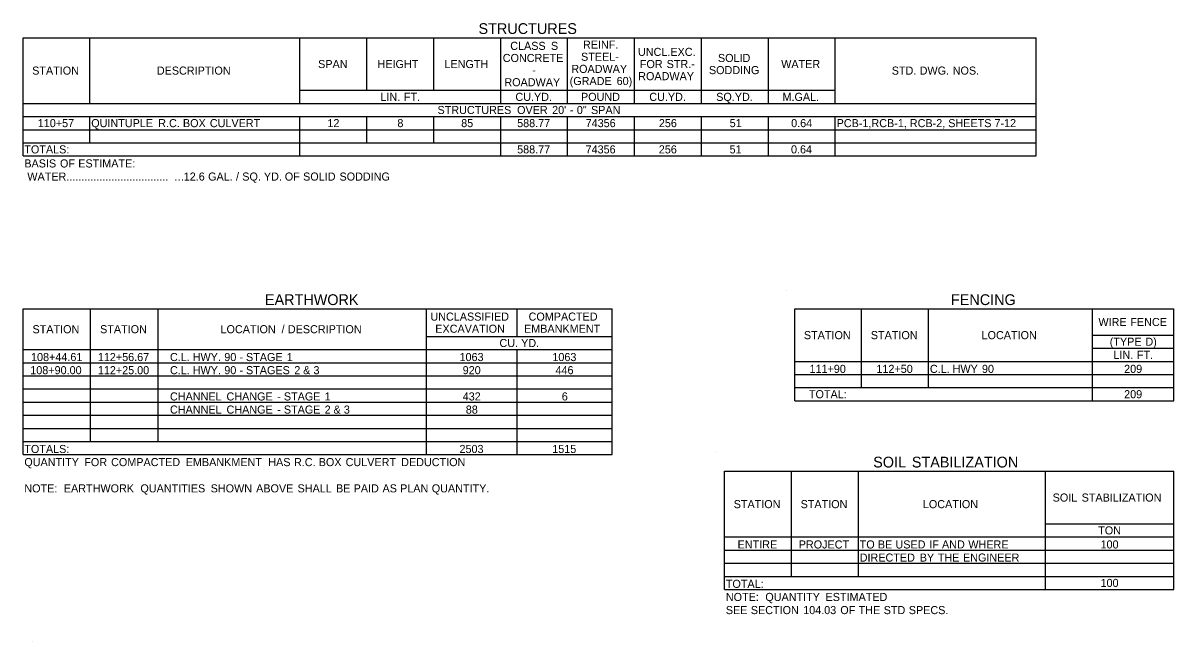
# Model space of a CAD drawing. Extents: x 120 to 5602, y 34 to 1048.
# Drawn here: x 2091 to 2946, y 556 to 1016 of the extents above; entities that cross this region are included whole.
import ezdxf

# ---------------------------------------------------------------- set-up
doc = ezdxf.new("R2010")
doc.units = 0
doc.layers.add('Default', color=7, linetype='Continuous')
doc.layers.add('STAMP', color=7, linetype='Continuous')

msp = doc.modelspace()

# ---------------------------------------------------------------- linework, layer by layer
at = {"layer": 'Default'}
for p, q in [((2091.12, 1005.05), (2843.82, 1005.05)), ((2091.12, 917.3), (2091.12, 1005.05)), ((2091.12, 917.3), (2091.12, 1005.05)), ((2140.85, 956.3), (2140.85, 1005.05)), ((2296.85, 956.3), (2296.85, 1005.05)), ((2346.57, 966.05), (2346.57, 1005.05)), ((2396.3, 966.05), (2396.3, 1005.05)), ((2446.02, 956.3), (2446.02, 1005.05)), ((2495.75, 956.3), (2495.75, 1005.05)), ((2545.47, 956.3), (2545.47, 1005.05)), ((2595.2, 956.3), (2595.2, 1005.05)), ((2644.92, 956.3), (2644.92, 1005.05)), ((2694.65, 956.3), (2694.65, 1005.05)), ((2843.82, 917.3), (2843.82, 1005.05)), ((2296.85, 966.05), (2694.65, 966.05)), ((2495.75, 956.3), (2495.75, 966.05)), ((2545.47, 956.3), (2545.47, 966.05)), ((2595.2, 956.3), (2595.2, 966.05)), ((2644.92, 956.3), (2644.92, 966.05)), ((2694.65, 956.3), (2694.65, 966.05)), ((2091.12, 956.3), (2843.82, 956.3)), ((2694.65, 956.3), (2843.82, 956.3)), ((2843.82, 946.55), (2843.82, 956.3)), ((2091.12, 946.55), (2843.82, 946.55)), ((2140.85, 927.05), (2140.85, 946.55)), ((2140.85, 927.05), (2140.85, 946.55)), ((2296.85, 917.3), (2296.85, 946.55)), ((2346.57, 927.05), (2346.57, 946.55)), ((2346.57, 927.05), (2346.57, 946.55)), ((2396.3, 927.05), (2396.3, 946.55)), ((2396.3, 927.05), (2396.3, 946.55)), ((2446.02, 917.3), (2446.02, 946.55)), ((2446.02, 917.3), (2446.02, 946.55)), ((2495.75, 917.3), (2495.75, 946.55)), ((2495.75, 917.3), (2495.75, 946.55)), ((2545.47, 917.3), (2545.47, 946.55)), ((2545.47, 917.3), (2545.47, 946.55)), ((2595.2, 917.3), (2595.2, 946.55)), ((2595.2, 917.3), (2595.2, 946.55)), ((2644.92, 917.3), (2644.92, 946.55)), ((2644.92, 917.3), (2644.92, 946.55)), ((2694.65, 936.8), (2694.65, 946.55)), ((2694.65, 917.3), (2694.65, 946.55)), ((2091.12, 936.8), (2843.82, 936.8)), ((2843.82, 917.3), (2843.82, 936.8)), ((2091.12, 927.05), (2843.82, 927.05)), ((2296.85, 917.3), (2296.85, 927.05)), ((2694.65, 917.3), (2694.65, 927.05)), ((2091.12, 917.3), (2843.82, 917.3)), ((2091.12, 803.76), (2528.9, 803.76)), ((2091.12, 695.54), (2091.12, 803.76)), ((2091.12, 695.54), (2091.12, 803.76)), ((2141.34, 705.29), (2141.34, 803.76)), ((2191.55, 705.29), (2191.55, 803.76)), ((2390.94, 695.54), (2390.94, 803.76)), ((2458.21, 783.29), (2458.21, 803.76)), ((2528.9, 695.54), (2528.9, 803.76)), ((2528.9, 695.54), (2528.9, 803.76)), ((2664.5, 803.76), (2946.28, 803.76)), ((2664.5, 735.51), (2664.5, 803.76)), ((2664.5, 735.51), (2664.5, 803.76)), ((2714.23, 745.26), (2714.23, 803.76)), ((2763.95, 745.26), (2763.95, 803.76)), ((2885.83, 735.51), (2885.83, 803.76)), ((2946.28, 784.26), (2946.28, 803.76)), ((2946.28, 735.51), (2946.28, 803.76)), ((2390.94, 783.29), (2528.9, 783.29)), ((2885.83, 784.26), (2946.28, 784.26)), ((2091.12, 773.54), (2528.9, 773.54)), ((2141.34, 705.29), (2141.34, 773.54)), ((2191.55, 773.54), (2390.94, 773.54)), ((2191.55, 705.29), (2191.55, 773.54)), ((2390.94, 705.29), (2390.94, 773.54)), ((2458.21, 695.54), (2458.21, 773.54)), ((2885.83, 774.51), (2946.28, 774.51)), ((2885.83, 774.51), (2946.28, 774.51)), ((2946.28, 755.01), (2946.28, 774.51)), ((2091.12, 763.79), (2528.9, 763.79)), ((2664.5, 764.76), (2946.28, 764.76)), ((2714.23, 745.26), (2714.23, 764.76)), ((2763.95, 745.26), (2763.95, 764.76)), ((2885.83, 735.51), (2885.83, 764.76)), ((2091.12, 754.04), (2528.9, 754.04)), ((2664.5, 755.01), (2946.28, 755.01)), ((2091.12, 744.29), (2528.9, 744.29)), ((2664.5, 745.26), (2946.28, 745.26)), ((2946.28, 735.51), (2946.28, 745.26)), ((2664.5, 735.51), (2946.28, 735.51)), ((2091.12, 734.54), (2528.9, 734.54)), ((2091.12, 724.79), (2528.9, 724.79)), ((2091.12, 715.04), (2528.9, 715.04)), ((2091.12, 705.29), (2141.34, 705.29)), ((2091.12, 705.29), (2528.9, 705.29)), ((2091.12, 695.54), (2528.9, 695.54)), ((2612.34, 683.15), (2946.28, 683.15)), ((2612.34, 595.4), (2612.34, 683.15)), ((2612.34, 595.4), (2612.34, 683.15)), ((2662.07, 605.15), (2662.07, 683.15)), ((2711.79, 605.15), (2711.79, 683.15)), ((2850.73, 595.4), (2850.73, 683.15)), ((2946.28, 595.4), (2946.28, 683.15)), ((2946.28, 595.4), (2946.28, 683.15)), ((2850.73, 644.15), (2946.28, 644.15)), ((2850.73, 595.4), (2850.73, 644.15)), ((2612.34, 634.4), (2946.28, 634.4)), ((2662.07, 605.15), (2662.07, 634.4)), ((2711.79, 605.15), (2711.79, 634.4)), ((2612.34, 624.65), (2946.28, 624.65)), ((2612.34, 614.9), (2946.28, 614.9)), ((2612.34, 605.15), (2662.07, 605.15)), ((2612.34, 605.15), (2946.28, 605.15)), ((2662.07, 605.15), (2711.79, 605.15)), ((2711.79, 605.15), (2850.73, 605.15)), ((2612.34, 595.4), (2946.28, 595.4))]:
    msp.add_line(p, q, dxfattribs=at)
at = {"layer": 'STAMP'}
for p, q in [((2658.65, 817.41), (2658.65, 817.41)), ((2606.49, 696.8), (2606.49, 696.8)), ((2097.85, 556.43), (2097.85, 556.43))]:
    msp.add_line(p, q, dxfattribs=at)

# ---------------------------------------------------------------- texts
at = {"layer": 'Default'}
for s, height, p in [('STRUCTURES', 8, (2429.55, 1007.88)), ('CLASS', 6, (2453.13, 996.05)), (' S', 6, (2481.14, 996.05)), ('REINF.', 6, (2507.16, 996.95)), ('CONCRETE', 6, (2447.57, 987.05)), ('STEEL-', 6, (2505.74, 987.95)), ('UNCL.EXC.', 6, (2548.03, 991.55)), ('SOLID', 6, (2607.46, 987.05)), ('STATION', 6, (2097.92, 977.68)), ('DESCRIPTION', 6, (2190.54, 977.68)), ('SPAN', 6, (2310.4, 982.55)), ('HEIGHT', 6, (2354.52, 982.55)), ('LENGTH', 6, (2404.25, 982.55)), ('ROADWAY', 6, (2498.48, 978.95)), ('FOR', 6, (2549.43, 982.55)), (' STR.-', 6, (2567.09, 982.55)), ('SODDING', 6, (2600.75, 978.05)), ('WATER', 6, (2654.44, 982.55)), ('STD.', 6, (2736.57, 977.68)), (' DWG.', 6, (2755.09, 977.68)), (' NOS.', 6, (2779.66, 977.68)), ('ROADWAY', 6, (2448.76, 969.05)), ('-', 6, (2469.52, 978.05)), ('(GRADE', 6, (2497.28, 969.95)), (' 60)', 6, (2529.94, 969.95)), ('ROADWAY', 6, (2548.21, 973.55)), ('LIN.', 6, (2356.65, 958.18)), (' FT.', 6, (2371.9, 958.18)), ('CU.YD.', 6, (2456.97, 958.18)), ('POUND', 6, (2505.68, 958.18)), ('CU.YD.', 6, (2556.42, 958.18)), ('SQ.YD.', 6, (2606.14, 958.18)), ('M.GAL.', 6, (2655.41, 958.18)), ('STRUCTURES', 6, (2399.09, 948.43)), (' OVER', 6, (2455.98, 948.43)), (" 20'", 6, (2482.03, 948.43)), (' -', 6, (2495.3, 948.43)), (' 0"', 6, (2500.36, 948.43)), (' SPAN', 6, (2510.91, 948.43)), ('110+57', 6, (2102.08, 938.68)), ('QUINTUPLE', 6, (2141.82, 938.68)), (' R.C.', 6, (2189.36, 938.68)), (' BOX', 6, (2207.72, 938.68)), (' CULVERT', 6, (2227.7, 938.68)), ('12', 6, (2317.27, 938.68)), ('8', 6, (2369.29, 938.68)), ('85', 6, (2416.67, 938.68)), ('588.77', 6, (2458.26, 938.68)), ('74356', 6, (2509.15, 938.68)), ('256', 6, (2563.54, 938.68)), ('51', 6, (2616.17, 938.68)), ('0.64', 6, (2661.84, 938.68)), ('PCB-1,RCB-1, RCB-2, SHEETS 7-12', 6, (2695.62, 938.68)), ('TOTALS:', 6, (2092.1, 919.18)), ('588.77', 6, (2458.26, 919.18)), ('74356', 6, (2509.11, 919.18)), ('256', 6, (2563.5, 919.18)), ('51', 6, (2616.08, 919.18)), ('0.64', 6, (2661.73, 919.18)), ('BASIS', 6, (2092.1, 908.75)), (' OF', 6, (2116.36, 908.75)), (' ESTIMATE:', 6, (2129.95, 908.75)), (' WATER..................................', 6, (2092.1, 899)), ('…', 6, (2203.11, 899)), ('12.6', 6, (2210.51, 899)), (' GAL.', 6, (2226.44, 899)), (' /', 6, (2247.14, 899)), (' SQ.', 6, (2251.8, 899)), (' YD.', 6, (2267.84, 899)), (' OF', 6, (2283.41, 899)), (' SOLID', 6, (2297, 899)), (' SODDING', 6, (2324.03, 899)), ('EARTHWORK', 8, (2270.88, 806.59)), ('FENCING', 8, (2780.58, 806.59)), ('UNCLASSIFIED', 6, (2393.81, 795.02)), ('COMPACTED', 6, (2466.75, 795.02)), ('WIRE', 6, (2890.15, 791.01)), (' FENCE', 6, (2911.62, 791.01)), ('STATION', 6, (2098.17, 785.65)), ('STATION', 6, (2148.38, 785.65)), ('LOCATION', 6, (2237.88, 785.65)), (' /', 6, (2280.99, 785.65)), (' DESCRIPTION', 6, (2285.65, 785.65)), ('EXCAVATION', 6, (2397.43, 786.02)), ('EMBANKMENT', 6, (2463.37, 786.02)), ('STATION', 6, (2671.3, 781.26)), ('STATION', 6, (2721.03, 781.26)), ('LOCATION', 6, (2803.34, 781.26)), ('CU.', 6, (2445.12, 775.41)), (' YD.', 6, (2458.98, 775.41)), ('(TYPE', 6, (2898.55, 776.39)), (' D)', 6, (2922.82, 776.39)), ('108+44.61', 6, (2097.08, 764.99)), ('112+56.67', 6, (2146.71, 764.99)), ('C.L.', 6, (2200.32, 764.99)), (' HWY.', 6, (2214.96, 764.99)), (' 90', 6, (2238.45, 764.99)), (' STAGE', 6, (2254.55, 764.99)), (' 1', 6, (2284.85, 764.99)), ('1063', 6, (2415.44, 764.99)), ('1063', 6, (2484.42, 764.99)), ('LIN.', 6, (2901.26, 766.64)), (' FT.', 6, (2916.52, 766.64)), ('108+90.00', 6, (2096.51, 755.24)), ('112+25.00', 6, (2146.72, 755.24)), ('C.L.', 6, (2200.32, 755.24)), (' HWY.', 6, (2214.96, 755.24)), (' 90', 6, (2238.45, 755.24)), (' -', 6, (2249.69, 764.99)), (' STAGES', 6, (2254.55, 755.24)), (' 2', 6, (2290.45, 755.24)), (' &', 6, (2297, 755.24)), (' 3', 6, (2304.72, 755.24)), ('920', 6, (2417.79, 755.24)), ('446', 6, (2486.75, 755.24)), ('111+90', 6, (2675.47, 756.21)), ('112+50', 6, (2725.2, 756.21)), ('C.L.', 6, (2764.93, 756.21)), (' HWY', 6, (2779.57, 756.21)), (' 90', 6, (2801.39, 756.21)), ('209', 6, (2909.25, 756.21)), (' -', 6, (2249.69, 755.24)), ('CHANNEL', 6, (2200.32, 735.74)), (' CHANGE', 6, (2240.09, 735.74)), (' -', 6, (2277.84, 735.74)), (' STAGE', 6, (2282.7, 735.74)), (' 1', 6, (2313, 735.74)), ('432', 6, (2417.81, 735.74)), ('6', 6, (2491.42, 735.74)), ('TOTAL:', 6, (2675.06, 737.39)), ('209', 6, (2909.25, 737.39)), ('CHANNEL', 6, (2200.32, 725.99)), (' CHANGE', 6, (2240.09, 725.99)), (' -', 6, (2277.84, 725.99)), (' STAGE', 6, (2282.7, 725.99)), (' 2', 6, (2313, 725.99)), (' &', 6, (2319.55, 725.99)), (' 3', 6, (2327.28, 725.99)), ('88', 6, (2420.1, 725.99)), ('TOTALS:', 6, (2092.1, 696.74)), ('2503', 6, (2415.43, 696.74)), ('1515', 6, (2484.36, 696.74)), ('QUANTITY', 6, (2092.1, 686.99)), (' FOR', 6, (2134.42, 686.99)), (' COMPACTED', 6, (2154.34, 686.99)), (' EMBANKMENT', 6, (2209.79, 686.99)), (' HAS', 6, (2271.11, 686.99)), (' R.C.', 6, (2290.24, 686.99)), (' BOX', 6, (2308.6, 686.99)), (' CULVERT', 6, (2328.58, 686.99)), (' DEDUCTION', 6, (2369.87, 686.99)), ('SOIL', 8, (2722.79, 685.98)), (' STABILIZATION', 8, (2748.54, 685.98)), ('NOTE:', 6, (2092.1, 667.49)), ('  EARTHWORK', 6, (2116.99, 667.49)), (' QUANTITIES', 6, (2176.12, 667.49)), (' SHOWN', 6, (2228.32, 667.49)), (' ABOVE', 6, (2262.1, 667.49)), (' SHALL', 6, (2292.87, 667.49)), (' BE', 6, (2321.46, 667.49)), (' PAID', 6, (2334.53, 667.49)), (' AS', 6, (2355.98, 667.49)), (' PLAN', 6, (2369.05, 667.49)), (' QUANTITY.', 6, (2392.59, 667.49)), ('STATION', 6, (2619.14, 655.78)), ('STATION', 6, (2668.87, 655.78)), ('LOCATION', 6, (2759.71, 655.78)), ('SOIL', 6, (2856.12, 660.65)), (' STABILIZATION', 6, (2875.43, 660.65)), ('TON', 6, (2889.99, 636.28)), ('ENTIRE', 6, (2622.06, 625.85)), ('PROJECT', 6, (2667.45, 625.85)), ('TO', 6, (2712.77, 625.85)), (' BE', 6, (2724.03, 625.85)), (' USED', 6, (2737.1, 625.85)), (' IF', 6, (2762.28, 625.85)), (' AND', 6, (2771.67, 625.85)), (' WHERE', 6, (2791.25, 625.85)), ('100', 6, (2891.72, 625.85)), ('DIRECTED', 6, (2712.77, 616.1)), (' BY', 6, (2755.17, 616.1)), (' THE', 6, (2768.62, 616.1)), (' ENGINEER', 6, (2787.27, 616.1)), ('TOTAL:', 6, (2613.32, 596.6)), ('100', 6, (2891.72, 597.28)), ('NOTE:', 6, (2613.32, 586.85)), ('  QUANTITY', 6, (2638.2, 586.85)), (' ESTIMATED', 6, (2685.18, 586.85)), ('SEE', 6, (2613.32, 577.1)), (' SECTION', 6, (2629.65, 577.1)), (' 104.03', 6, (2668.56, 577.1)), (' OF', 6, (2696.13, 577.1)), (' THE', 6, (2709.72, 577.1)), (' STD', 6, (2728.37, 577.1)), (' SPECS.', 6, (2747.02, 577.1))]:
    msp.add_text(s, height=height, dxfattribs=at).set_placement(p)

doc.saveas('drawing.dxf')
